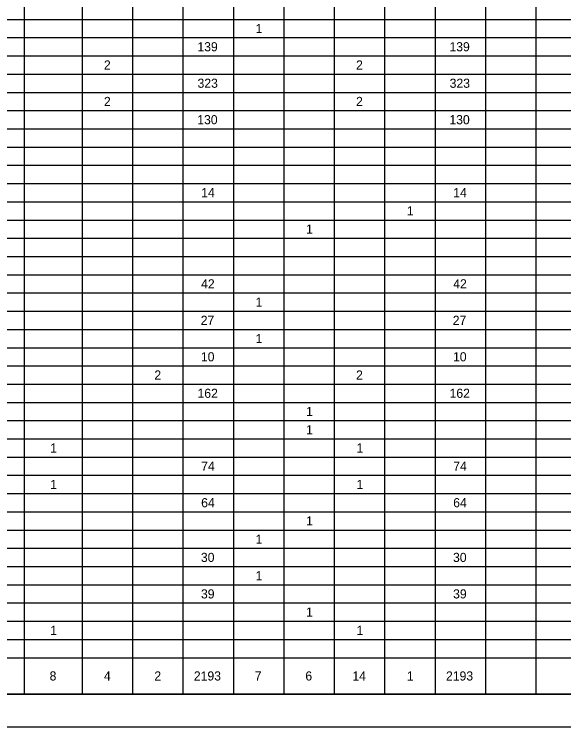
# Model space of a CAD drawing. Extents: x 0 to 34, y 0 to 22.
# Drawn here: x 17.13 to 25.56, y 0 to 10.94 of the extents above; entities that cross this region are included whole.
import ezdxf

# ---------------------------------------------------------------- set-up
doc = ezdxf.new("R2010")
doc.units = 0
for name, color, linetype in [('SH_Border', 7, 'Continuous'), ('SH_Cut_Line', 7, 'Continuous'), ('SH_Text', 7, 'Continuous')]:
    doc.layers.add(name, color=color, linetype=linetype)

msp = doc.modelspace()

# ---------------------------------------------------------------- linework, layer by layer
at = {"layer": 'SH_Border'}
msp.add_lwpolyline([(1.5, 21.5), (33.5, 21.5), (33.5, 0.5), (1.5, 0.5)], close=True, dxfattribs=at)
at = {"layer": 'SH_Cut_Line'}
msp.add_lwpolyline([(0, 0), (34, 0), (34, 22), (0, 22)], close=True, dxfattribs=at)
at = {"layer": 'SH_Text'}
for p, q in [((17.279, 21.5), (17.279, 0.5)), ((18.168, 21.5), (18.168, 0.5)), ((18.942, 21.5), (18.942, 0.5)), ((19.716, 21.5), (19.716, 0.5)), ((20.491, 21.5), (20.491, 0.5)), ((21.265, 21.5), (21.265, 0.5)), ((22.039, 21.5), (22.039, 0.5)), ((22.813, 21.5), (22.813, 0.5)), ((23.587, 21.5), (23.587, 0.5)), ((24.361, 21.5), (24.361, 0.5)), ((25.135, 21.5), (25.135, 0.5)), ((1.5, 10.86), (31.724, 10.86)), ((1.5, 10.58), (31.724, 10.58)), ((1.5, 10.3), (31.724, 10.3)), ((1.5, 10.02), (31.724, 10.02)), ((1.5, 9.74), (31.724, 9.74)), ((1.5, 9.46), (31.724, 9.46)), ((1.5, 9.18), (31.724, 9.18)), ((1.5, 8.9), (31.724, 8.9)), ((1.5, 8.62), (31.724, 8.62)), ((1.5, 8.34), (31.724, 8.34)), ((1.5, 8.06), (31.724, 8.06)), ((1.5, 7.78), (31.724, 7.78)), ((1.5, 7.5), (31.724, 7.5)), ((1.5, 7.22), (31.724, 7.22)), ((1.5, 6.94), (31.724, 6.94)), ((1.5, 6.66), (31.724, 6.66)), ((1.5, 6.38), (31.724, 6.38)), ((1.5, 6.1), (31.724, 6.1)), ((1.5, 5.82), (31.724, 5.82)), ((1.5, 5.54), (31.724, 5.54)), ((1.5, 5.26), (31.724, 5.26)), ((1.5, 4.98), (31.724, 4.98)), ((1.5, 4.7), (31.724, 4.7)), ((1.5, 4.42), (31.724, 4.42)), ((1.5, 4.14), (31.724, 4.14)), ((1.5, 3.86), (31.724, 3.86)), ((1.5, 3.58), (31.724, 3.58)), ((1.5, 3.3), (31.724, 3.3)), ((1.5, 3.02), (31.724, 3.02)), ((1.5, 2.74), (31.724, 2.74)), ((1.5, 2.46), (31.724, 2.46)), ((1.5, 2.18), (31.724, 2.18)), ((1.5, 1.9), (31.724, 1.9)), ((1.5, 1.62), (31.724, 1.62)), ((1.5, 1.34), (31.724, 1.34)), ((1.5, 1.06), (31.724, 1.06)), ((1.5, 0.5), (31.724, 0.5))]:
    msp.add_line(p, q, dxfattribs=at)

# ---------------------------------------------------------------- texts
for s, p in [('1', (20.832, 10.65)), ('139', (19.938, 10.37)), ('139', (23.808, 10.37)), ('2', (18.503, 10.09)), ('2', (22.374, 10.09)), ('323', (19.94, 9.81)), ('323', (23.811, 9.81)), ('2', (18.503, 9.53)), ('2', (22.374, 9.53)), ('130', (19.936, 9.25)), ('130', (23.807, 9.25)), ('14', (19.996, 8.13)), ('14', (23.866, 8.13)), ('1', (23.154, 7.85)), ('1', (21.606, 7.57)), ('42', (19.995, 6.73)), ('42', (23.866, 6.73)), ('1', (20.832, 6.45)), ('27', (19.989, 6.17)), ('27', (23.859, 6.17)), ('1', (20.832, 5.89)), ('10', (19.992, 5.61)), ('10', (23.863, 5.61)), ('2', (19.277, 5.33)), ('2', (22.374, 5.33)), ('162', (19.94, 5.05)), ('162', (23.81, 5.05)), ('1', (21.606, 4.77)), ('1', (21.606, 4.49)), ('1', (17.678, 4.21)), ('1', (22.38, 4.21)), ('74', (19.996, 3.93)), ('74', (23.866, 3.93)), ('1', (17.678, 3.65)), ('1', (22.38, 3.65)), ('64', (19.996, 3.37)), ('64', (23.866, 3.37)), ('1', (21.606, 3.09)), ('1', (20.832, 2.81)), ('30', (19.992, 2.53)), ('30', (23.863, 2.53)), ('1', (20.832, 2.25)), ('39', (19.993, 1.97)), ('39', (23.864, 1.97)), ('1', (21.606, 1.69)), ('1', (17.678, 1.41)), ('1', (22.38, 1.41)), ('8', (17.669, 0.71)), ('4', (18.503, 0.71)), ('2', (19.277, 0.71)), ('2193', (19.884, 0.71)), ('7', (20.819, 0.71)), ('6', (21.596, 0.71)), ('14', (22.318, 0.71)), ('1', (23.154, 0.71)), ('2193', (23.755, 0.71))]:
    msp.add_text(s, height=0.14, dxfattribs=at).set_placement(p)

doc.saveas('drawing.dxf')
